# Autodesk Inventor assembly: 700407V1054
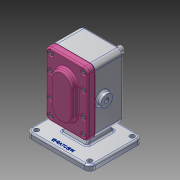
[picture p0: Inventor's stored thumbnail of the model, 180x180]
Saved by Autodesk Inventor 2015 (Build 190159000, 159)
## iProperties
Created: 2020-04
Part Number: 700407V1054
Document SubType Name: Assembly
Designer: 1019876
Author: 1019876
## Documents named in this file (11)
- C:\Users\1019876\Desktop\700407V1054\700407V1054.iam
- C:\Users\1019876\Desktop\700407V1054\700407V1054.ipt
- C:\Users\1019876\Desktop\700407V1054\개스킷.ipt
- C:\Users\1019876\Desktop\700407V1054\메인축.ipt
- C:\Users\1019876\Desktop\700407V1054\베어링부시.ipt
- C:\Users\1019876\Desktop\700407V1054\볼트 M5.ipt
- C:\Users\1019876\Desktop\700407V1054\서브축.ipt
- C:\Users\1019876\Desktop\700407V1054\스퍼기어.ipt
- C:\Users\1019876\Desktop\700407V1054\오일 실 16 28 7.ipt
- C:\Users\1019876\Desktop\700407V1054\커버.ipt
- C:\Users\1019876\Desktop\700407V1054\키 6 x 6 x 18.ipt
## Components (2 placed, 2 different names)
1. 700407V1054:1
2. 개스킷:1
